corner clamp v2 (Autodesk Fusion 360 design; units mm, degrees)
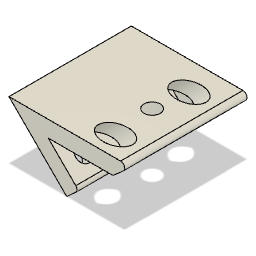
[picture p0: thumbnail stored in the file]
sketch "Sketch1" plane through (0, 0, 0) normal (0, 0, 1) x axis (1, 0, 0)
  line L1 (14.1421, -14.1421) -> (0, 0)
  line L2 (20, 0) -> (0, 0)
  line L3 (0, -28.2843) -> (14.1421, -14.1421)
  line L4 (-14.1421, -14.1421) -> (0, -28.2843)
  line L5 (0, 0) -> (-14.1421, -14.1421)
  line L6 (30, 0) -> (0, 0)
  line L7 (14.1421, -14.1421) -> (30, 0)
  point P1 (0, 0)
  point P2 (0, 0)
  point P7 (0, 0)
  point P8 (0, 0)
  point P3 (14.1421, -14.1421)
  point P5 (0, -28.2843)
  point P6 (-14.1421, -14.1421)
  point P9 (30, 0)
  horizontal L2
  coincident P1 P2
  perpendicular L1 L3
  perpendicular L3 L4
  coincident P1 P7
  coincident P1 P8
  parallel L2 L6
  dimension "d1" angle L1 L2 = 45
  dimension "d2" distance P2 P3 = 20
  dimension "d3" distance P3 P5 = 20
  dimension "d4" distance P5 P6 = 20
  dimension "d5" distance P8 P9 = 30
extrude "Extrude1" new body sketch "Sketch1" profile of L1 L6 L7 along normal blind 30
sketch "Sketch2" plane through (0, 0, 30) normal (0, 0, 1) x axis (1, 0, 0)
  line L1 (14.1421, -14.1421) -> (0, 0)
  line L2 (30, 0) -> (14.1421, -14.1421)
  line L3 (0, 0) -> (30, 0)
  line L4 (25.5147, -4) -> (9.6569, -4)
  line L5 (17.1323, -11.4755) -> (9.6569, -4)
  point P6 (25.5147, -4)
  point P7 (17.1323, -11.4755)
  coincident L2 P6
  horizontal L4
  coincident L2 P7
  parallel L1 L5
  dimension "d10" distance L1 L5 = 4
  dimension "d11" distance L3 L4 = 4
extrude "Extrude2" cut sketch "Sketch2" profile of L2 L4 L5 against normal blind 28
sketch "Sketch3" plane through (2.8284, 2.8284, 0) normal (0.7071, 0.7071, 0) x axis (0, 0, -1)
  line L1 (-30, -20.2288) -> (-30, -9.6569)
  line L2 (-2, -20.2288) -> (-30, -20.2288)
  line L3 (-2, -9.6569) -> (-2, -20.2288)
  line L4 (-30, -9.6569) -> (-2, -9.6569)
  line L5 (-30, -14.9428) -> (-2, -14.9428)
  circle C1 centre (-7, -14.9428) radius 2
  circle C2 centre (-25, -14.9428) radius 2
  circle C3 centre (-25, -14.9428) radius 3
  circle C4 centre (-7, -14.9428) radius 3
  point P6 (-2, -14.9428)
  point P7 (-30, -14.9428)
  point P8 (-7, -14.9428)
  point P9 (-25, -14.9428)
  midpoint L3 P6
  midpoint L1 P7
  coincident L5 P8
  coincident L5 P9
  dimension "d14" diameter C1 = 4
  dimension "d15" diameter C2 = 4
  dimension "d16" distance P7 P9 = 5
  dimension "d17" distance L3 P8 = 5
  dimension "d22" = 1
  dimension "d23" = 1
extrude "Extrude3" cut sketch "Sketch3" profile of C1 C2 against normal blind 19
extrude "Extrude4" cut sketch "Sketch3" profile of C1 C2 along normal blind 19
extrude "Extrude5" cut sketch "Sketch3" profile of C1 C2 C3 C4 along normal blind 28
sketch "Sketch4" plane through (0, 0, 0) normal (0, 1, 0) x axis (-1, 0, 0)
  line L1 (0, 0) -> (-30, 0)
  line L2 (0, 30) -> (0, 0)
  line L3 (-30, 30) -> (0, 30)
  line L4 (-30, 0) -> (-30, 30)
  line L5 (0, 15) -> (-30, 15)
  line L6 (0, 30) -> (-30, 30)
  closed curve K1 centre (-21.1323, 7)
  closed curve K2 centre (-21.1323, 25)
  circle C1 centre (-20.1073, 15) radius 2
  point P8 (-30, 15)
  point P9 (0, 15)
  point P12 (-20.1073, 15)
  coincident L4 P8
  coincident L2 P9
  perpendicular L2 L5
  coincident L5 P12
  dimension "d26" distance L1 L5 = 15 (= "30.00 mm / 2")
  dimension "d27" distance L1 L6 = 30
  dimension "d28" diameter C1 = 4
extrude "Extrude6" cut sketch "Sketch4" profile of C1 against normal blind 7
fillet "Fillet1" radius 1
fillet "Fillet2" radius 1
fillet "Fillet3" radius 1
fillet "Fillet4" radius 1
